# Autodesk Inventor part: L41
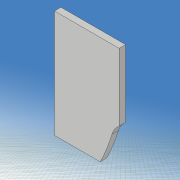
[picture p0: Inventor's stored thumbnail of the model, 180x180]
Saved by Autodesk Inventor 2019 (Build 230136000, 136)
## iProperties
Created: 2021-05
Part Number: L41
Material: 一般
Document SubType Name: Modeling
Designer: kikut
Density: 1 g/cm^3
Appearance: 既定
Mass: 0.00934248 g
Surface Area: 0.426451 cm^2
Volume: 0.00934248 cm^3
Author: kikut
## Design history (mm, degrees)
sketch "スケッチ1"
  geometry: L1 (80, 60)-(-80, 60); L2 (-80, 60)-(-80, -60); L3 (-80, -60)-(80, -60); L4 (80, -60)-(80, 60); L5 (80, 60)-(-80, -60); L6 (-80, 60)-(80, -60); 1 further point
  constraints: 12 end point, 2 midpoint, 2 parallel, 1 horizontal, 1 perpendicular
  dimensions: "d0" = 160 distance of L2.end L3.end; "d1" = 120 distance of L1.end L2.end
extrude "押し出し1" new body sketch "スケッチ1" stored distance "d2" = 0.6; taper "d3" = 0 deg
sketch "スケッチ2"
  geometry: L1 (-140, 0)-(140, 0) reference; L2 (0, -54)-(20, -30); L3 (0, 54)-(20, 30); L4 (0, -3)-(6.514, -3); L5 (6.514, -3)-(16, -6); L6 (16, -6)-(24, -3); L7 (24, -3)-(33.716, -3); L8 (0, 3)-(6.514, 3); L9 (6.514, 3)-(16, 6); L10 (16, 6)-(24, 3); L11 (24, 3)-(33.716, 3); L12 (0, -98)-(0, 98) reference; L13 (-100, -70)-(100, -70); L14 (100, -70)-(100, 70); L15 (100, 70)-(-100, 70); L16 (-100, 70)-(-100, -70); L17 (-100, -70)-(100, 70); L18 (100, -70)-(-100, 70); A1 r 60 centre (54.312, 28.5) between (0, 54) and (0, 3); A2 r 60 centre (54.312, -28.5) between (0, -3) and (0, -54); A3 r 18.111 centre (18, -12) between (20, -30) and (33.716, -3); A4 r 18.111 centre (18, 12) between (33.716, 3) and (20, 30); 1 further point
  constraints: 32 end point, 8 point on circle, 8 symmetric about line, 4 centre point, 3 horizontal, 2 collinear, 2 midpoint, 2 parallel, 1 perpendicular
  dimensions: "d5" = 60 radius of A1; "d6" = 6 distance of L8.start L4.start; "d7" = 108 distance of L3.start L2.start; "d8" = 0 horizontal distance of L3.start L8.start; "d9" = 60 distance of L3.end L2.end; "d10" = 0 horizontal distance of point (0, 0) L3.start; "d11" = 20 horizontal distance of L3.start L3.end; "d12" = 24 distance of A4.centre A3.centre; "d13" = 6 distance of L11.end L7.end; "d14" = 12 distance of L9.end L5.end; "d15" = 16 distance from line of L12 L5.end; "d16" = 24 distance from line of L6.end L12; "d17" = 200 distance of L14.end L15.end; "d18" = 140 distance of L15.end L13.start; "d30" = 18 distance from line of L12 A4.centre
extrude "押し出し2" cut sketch "スケッチ2" stored distance "d19" = 10; taper "d20" = 0 deg
sketch "スケッチ3"
  geometry: L1 (49.705, -17.97)-(33.948, -15.191); L2 (33.948, -15.191)-(34.295, -13.222); L3 (34.295, -13.222)-(50.052, -16); L4 (50.052, -16)-(49.705, -17.97); L5 (49.705, -17.97)-(34.295, -13.222); L6 (33.948, -15.191)-(50.052, -16); L7 (50.052, 16)-(34.295, 13.222); L8 (34.295, 13.222)-(33.948, 15.191); L9 (33.948, 15.191)-(49.705, 17.97); L10 (49.705, 17.97)-(50.052, 16); L11 (50.052, 16)-(33.948, 15.191); L12 (34.295, 13.222)-(49.705, 17.97); L13 (-112, 0)-(112, 0) reference; L14 (0, -84)-(0, 84) reference; 3 further points
  constraints: 24 end point, 4 midpoint, 4 parallel, 2 perpendicular, 2 symmetric about line
  dimensions: "d21" = 2 distance of L3.end L1.start; "d22" = 2 distance of L9.end L7.start; "d23" = 16 distance of L8.end L9.end; "d24" = 42 distance from line of L14 point (42, 15.596); "d26" = 10 deg angle of L7 L13; "d62" = 16 distance from line of L3.end L13
extrude "押し出し3" join sketch "スケッチ3" distance "d27" = 0.6; taper "d28" = 0 deg
fillet "フィレット1" dims "d31" = 2
fillet "フィレット2" dims "d32" = 1
sketch "スケッチ7"
  geometry: L1 (-20, 60)-(80, 60); L2 (80, 60)-(80, -60); L3 (80, -60)-(-20, -60); L4 (-20, -60)-(-20, 60); L5 (0, -82.207)-(0, 85.793) reference; L6 (-40, 0)-(100, 0) reference; L7 (30, -10)-(36, -10); L8 (36, -10)-(36, -20); L9 (36, -20)-(30, -20); L10 (30, -20)-(30, -10); 1 further point
  constraints: 16 end point, 4 parallel, 2 horizontal, 2 perpendicular, 1 other
  dimensions: "d80" = 120 distance of L3.end L1.start; "d81" = 20 distance between parallel lines of L5 L4; "d82" = 100 distance of L1.start L1.end; "d84" = 6 distance of L8.end L9.end; "d85" = 10 distance of L7.end L8.end; "d86" = 50 distance between parallel lines of L4 L10; "d93" = 40 distance between parallel lines of L3 L9
extrude "押し出し5" cut sketch "スケッチ7" stored distance "d87" = 10; taper "d88" = 0 deg
node "ソリッド1"
